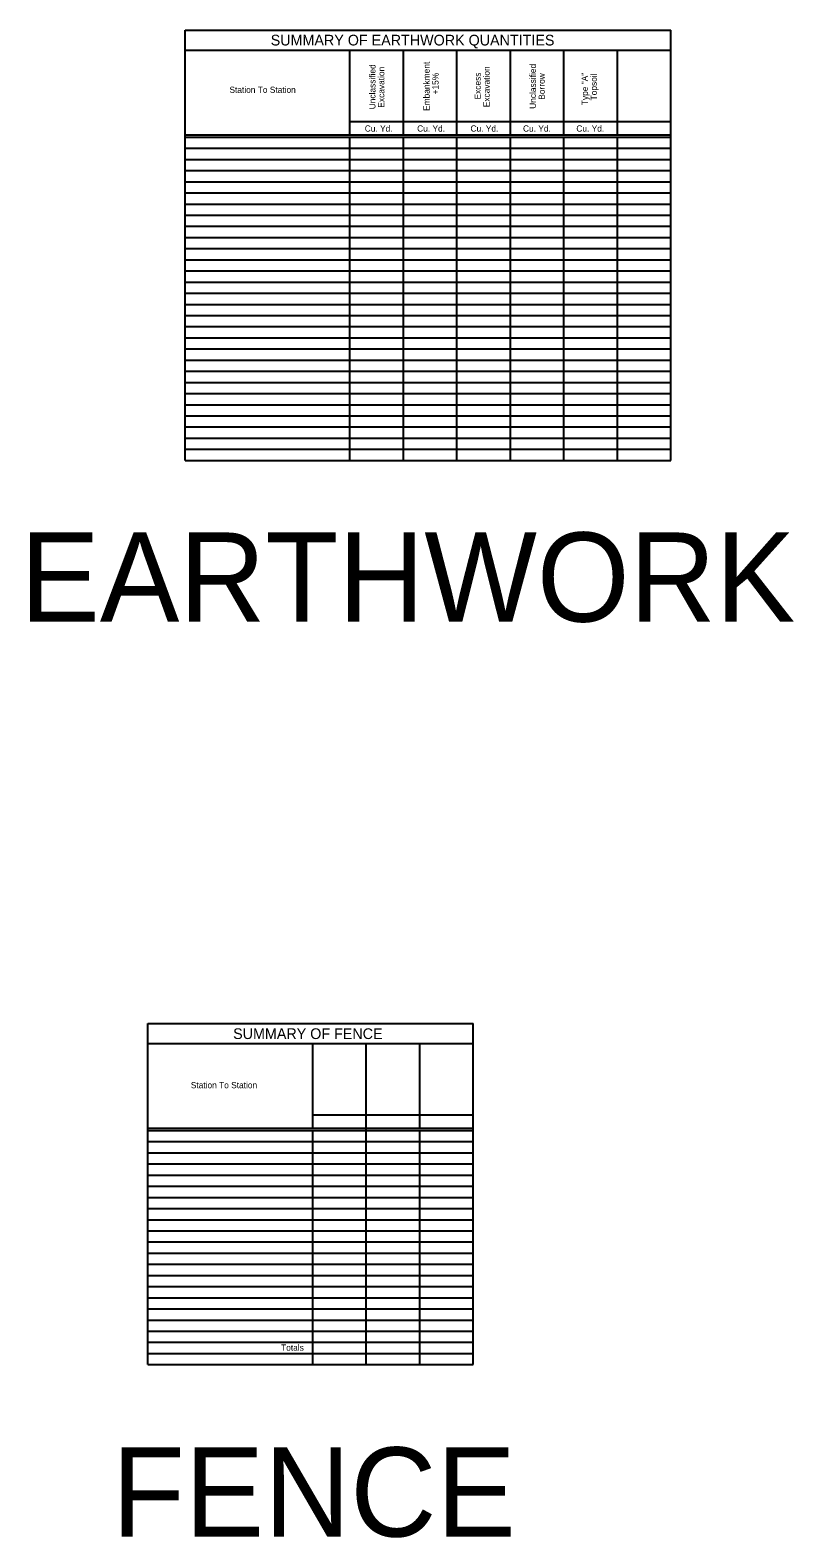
# Model space of a CAD drawing. Extents: x 1790274 to 1791453, y 1790011 to 1790884.
# Drawn here: x 1790859.4 to 1791030.8, y 1790010.5 to 1790348.7 of the extents above; entities that cross this region are included whole.
import ezdxf

# ---------------------------------------------------------------- set-up
doc = ezdxf.new("R2010")
doc.units = 0
doc.layers.add('Level 1', color=7, linetype='Continuous')
doc.layers.add('Level 2', color=7, linetype='Continuous')

msp = doc.modelspace()

# ---------------------------------------------------------------- linework, layer by layer
at = {"layer": 'Level 1'}
for p, q in [((1790894.18, 1790348.67), (1791003.18, 1790348.67)), ((1790894.18, 1790252.17), (1790894.18, 1790348.67)), ((1791003.18, 1790252.17), (1791003.18, 1790348.67)), ((1790894.18, 1790344.17), (1791003.18, 1790344.17)), ((1790931.18, 1790325.17), (1790931.18, 1790344.17)), ((1790943.18, 1790325.17), (1790943.18, 1790344.17)), ((1790955.18, 1790325.17), (1790955.18, 1790344.17)), ((1790967.18, 1790325.17), (1790967.18, 1790344.17)), ((1790979.18, 1790325.17), (1790979.18, 1790344.17)), ((1790991.18, 1790325.17), (1790991.18, 1790344.17)), ((1791003.18, 1790325.17), (1791003.18, 1790344.17)), ((1790931.18, 1790328.17), (1791003.18, 1790328.17)), ((1790894.18, 1790325.17), (1791003.18, 1790325.17)), ((1790894.18, 1790324.67), (1791003.18, 1790324.67)), ((1790931.18, 1790252.17), (1790931.18, 1790324.67)), ((1790943.18, 1790252.17), (1790943.18, 1790324.67)), ((1790955.18, 1790252.17), (1790955.18, 1790324.67)), ((1790967.18, 1790252.17), (1790967.18, 1790324.67)), ((1790979.18, 1790252.17), (1790979.18, 1790324.67)), ((1790991.18, 1790252.17), (1790991.18, 1790324.67)), ((1791003.18, 1790252.17), (1791003.18, 1790324.67)), ((1790894.18, 1790322.17), (1791003.18, 1790322.17)), ((1790894.18, 1790319.67), (1791003.18, 1790319.67)), ((1790894.18, 1790317.17), (1791003.18, 1790317.17)), ((1790894.18, 1790314.67), (1791003.18, 1790314.67)), ((1790894.18, 1790312.17), (1791003.18, 1790312.17)), ((1790894.18, 1790309.67), (1791003.18, 1790309.67)), ((1790894.18, 1790307.17), (1791003.18, 1790307.17)), ((1790894.18, 1790304.67), (1791003.18, 1790304.67)), ((1790894.18, 1790302.17), (1791003.18, 1790302.17)), ((1790894.18, 1790299.67), (1791003.18, 1790299.67)), ((1790894.18, 1790297.17), (1791003.18, 1790297.17)), ((1790894.18, 1790294.67), (1791003.18, 1790294.67)), ((1790894.18, 1790292.17), (1791003.18, 1790292.17)), ((1790894.18, 1790289.67), (1791003.18, 1790289.67)), ((1790894.18, 1790287.17), (1791003.18, 1790287.17)), ((1790894.18, 1790284.67), (1791003.18, 1790284.67)), ((1790894.18, 1790282.17), (1791003.18, 1790282.17)), ((1790894.18, 1790279.67), (1791003.18, 1790279.67)), ((1790894.18, 1790277.17), (1791003.18, 1790277.17)), ((1790894.18, 1790274.67), (1791003.18, 1790274.67)), ((1790894.18, 1790272.17), (1791003.18, 1790272.17)), ((1790894.18, 1790272.17), (1791003.18, 1790272.17)), ((1790894.18, 1790269.67), (1791003.18, 1790269.67)), ((1790894.18, 1790267.17), (1791003.18, 1790267.17)), ((1790894.18, 1790264.67), (1791003.18, 1790264.67)), ((1790894.18, 1790262.17), (1791003.18, 1790262.17)), ((1790894.18, 1790259.67), (1791003.18, 1790259.67)), ((1790894.18, 1790257.17), (1791003.18, 1790257.17)), ((1790894.18, 1790254.67), (1791003.18, 1790254.67)), ((1790894.18, 1790252.17), (1791003.18, 1790252.17)), ((1790885.85, 1790125.88), (1790958.85, 1790125.88)), ((1790885.85, 1790049.38), (1790885.85, 1790125.88)), ((1790958.85, 1790049.38), (1790958.85, 1790125.88)), ((1790885.85, 1790121.38), (1790958.85, 1790121.38)), ((1790922.85, 1790102.38), (1790922.85, 1790121.38)), ((1790934.85, 1790102.38), (1790934.85, 1790121.38)), ((1790946.85, 1790102.38), (1790946.85, 1790121.38)), ((1790922.85, 1790105.38), (1790958.85, 1790105.38)), ((1790885.85, 1790102.38), (1790958.85, 1790102.38)), ((1790885.85, 1790101.88), (1790958.85, 1790101.88)), ((1790922.85, 1790049.38), (1790922.85, 1790101.88)), ((1790934.85, 1790049.38), (1790934.85, 1790102.38)), ((1790946.85, 1790049.38), (1790946.85, 1790101.88)), ((1790958.85, 1790049.38), (1790958.85, 1790101.88)), ((1790885.85, 1790099.38), (1790958.85, 1790099.38)), ((1790885.85, 1790096.88), (1790958.85, 1790096.88)), ((1790885.85, 1790094.38), (1790958.85, 1790094.38)), ((1790885.85, 1790091.88), (1790958.85, 1790091.88)), ((1790885.85, 1790089.38), (1790958.85, 1790089.38)), ((1790885.85, 1790086.88), (1790958.85, 1790086.88)), ((1790885.85, 1790084.38), (1790958.85, 1790084.38)), ((1790885.85, 1790081.88), (1790958.85, 1790081.88)), ((1790885.85, 1790079.38), (1790958.85, 1790079.38)), ((1790885.85, 1790076.88), (1790958.85, 1790076.88)), ((1790885.85, 1790074.38), (1790958.85, 1790074.38)), ((1790885.85, 1790071.88), (1790958.85, 1790071.88)), ((1790885.85, 1790069.38), (1790958.85, 1790069.38)), ((1790885.85, 1790066.88), (1790958.85, 1790066.88)), ((1790885.85, 1790064.38), (1790958.85, 1790064.38)), ((1790885.85, 1790061.88), (1790958.85, 1790061.88)), ((1790885.85, 1790059.38), (1790958.85, 1790059.38)), ((1790885.85, 1790056.88), (1790958.85, 1790056.88)), ((1790885.85, 1790054.38), (1790958.85, 1790054.38)), ((1790885.85, 1790051.88), (1790958.85, 1790051.88)), ((1790885.85, 1790049.38), (1790958.85, 1790049.38))]:
    msp.add_line(p, q, dxfattribs=at)

# ---------------------------------------------------------------- texts
at = {"layer": 'Level 2'}
for s, height, p in [('SUMMARY OF EARTHWORK QUANTITIES', 2.4, (1790913.4, 1790345.23)), ('Station To Station', 1.4, (1790904.14, 1790334.6)), ('Cu. Yd.', 1.4, (1790934.5, 1790325.91)), ('Cu. Yd.', 1.4, (1790946.26, 1790325.91)), ('Cu. Yd.', 1.4, (1790958.23, 1790325.91)), ('Cu. Yd.', 1.4, (1790970, 1790325.91)), ('Cu. Yd.', 1.4, (1790981.97, 1790325.91)), ('EARTHWORK', 20, (1790857.23, 1790216.01)), ('SUMMARY OF FENCE', 2.4, (1790904.97, 1790122.4)), ('Station To Station', 1.4, (1790895.47, 1790111.36)), ('Totals', 1.4, (1790915.73, 1790052.49)), ('FENCE', 20, (1790877.77, 1790010.81))]:
    msp.add_text(s, height=height, dxfattribs=at).set_placement(p)
for s, p in [('Embankment', (1790949.06, 1790330.55)), ('Unclassified', (1790936.9, 1790330.92)), ('Excavation', (1790938.9, 1790331.29)), ('+15%', (1790951.06, 1790334.26)), ('Excess', (1790960.53, 1790333.12)), ('Excavation', (1790962.53, 1790331.39)), ('Unclassified', (1790972.9, 1790331.02)), ('Borrow', (1790974.9, 1790333.07)), ('Type "A"', (1790984.57, 1790331.85)), ('Topsoil', (1790986.57, 1790332.92))]:
    msp.add_text(s, height=1.4, rotation=90, dxfattribs=at).set_placement(p)

doc.saveas('drawing.dxf')
